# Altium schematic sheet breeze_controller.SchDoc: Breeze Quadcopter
size A4; Author: myyerrol; Organization: Team MicroDynamics; Address1: NWPU; Address2: Xi'an; Address3: Shannxi; Address4: China; Revision: V0.1; SheetNumber: 1; SheetTotal: 5
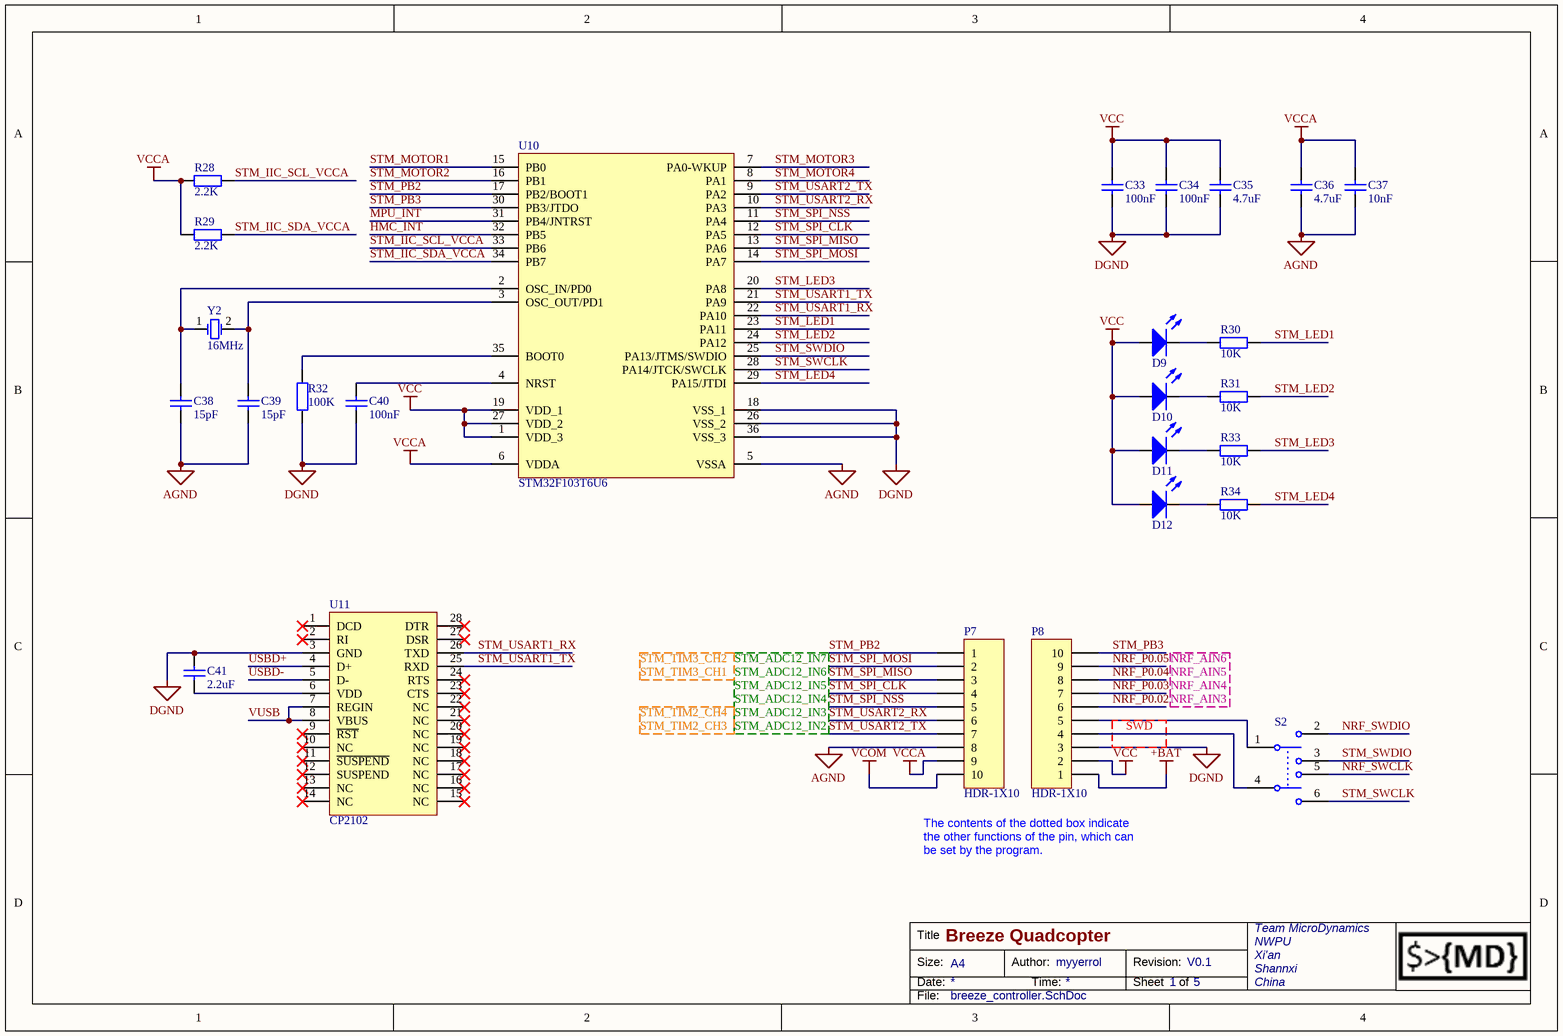
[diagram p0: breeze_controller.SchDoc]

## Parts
C33  value 100nF  [SMD-0603]  (hidden comment: CAP-0603)
C34  value 100nF  [SMD-0603]  (hidden comment: CAP-0603)
C35  value 4.7uF  [SMD-0603]  (hidden comment: CAP-0603)
C36  value 4.7uF  [SMD-0603]  (hidden comment: CAP-0603)
C37  value 10nF  [SMD-0603]  (hidden comment: CAP-0603)
C38  value 15pF  [SMD-0603]  (hidden comment: CAP-0603)
C39  value 15pF  [SMD-0603]  (hidden comment: CAP-0603)
C40  value 100nF  [SMD-0603]  (hidden comment: CAP-0603)
C41  value 2.2uF  [SMD-0603]  (hidden comment: CAP-0603)
D9  LED-0603  [SMD-0603]  (value not drawn)
D10  LED-0603  [SMD-0603]  (value not drawn)
D11  LED-0603  [SMD-0603]  (value not drawn)
D12  LED-0603  [SMD-0603]  (value not drawn)
P7  HDR-1X10  [HDR-1X10]
P8  HDR-1X10  [HDR-1X10]
R28  value 2.2K  [SMD-0603]  (hidden comment: RES-0603)
R29  value 2.2K  [SMD-0603]  (hidden comment: RES-0603)
R30  value 10K  [SMD-0603]  (hidden comment: RES-0603)
R31  value 10K  [SMD-0603]  (hidden comment: RES-0603)
R32  value 100K  [SMD-0603]  (hidden comment: RES-0603)
R33  value 10K  [SMD-0603]  (hidden comment: RES-0603)
R34  value 10K  [SMD-0603]  (hidden comment: RES-0603)
S2  MSS-22D18G2  [MSS-22D18G2]  (value not drawn)
U10  STM32F103T6U6  [VFQFPN-36]
U11  CP2102  [QFN-28]
Y2  value 16MHz  [SMD-5032]  (hidden comment: XTAL-5032)

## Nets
+BAT: P8.1
AGND: C36.2 C37.2 C38.2 C39.2 P7.8 U10.5(VSSA)
DGND: C33.2 C34.2 C35.2 C40.2 C41.2 P8.3 R32.2 U10.18(VSS_1) U10.26(VSS_2) U10.36(VSS_3) U11.3(GND)
VCC: C33.1 C34.1 C35.1 D9.1(A) D10.1(A) D11.1(A) D12.1(A) P8.2 U10.1(VDD_3) U10.19(VDD_1) U10.27(VDD_2)
VCCA: C36.1 C37.1 P7.9 R28.1 R29.1 U10.6(VDDA)
VCOM: P7.10
HMC_INT: U10.32(PB5)
MPU_INT: U10.31(PB4/JNTRST)
NRF_P0.02: P8.6
NRF_P0.03: P8.7
NRF_P0.04: P8.8
NRF_P0.05: P8.9
NRF_SWCLK: S2.5
NRF_SWDIO: S2.2
STM_IIC_SCL_VCCA: R28.2 U10.33(PB6)
STM_IIC_SDA_VCCA: R29.2 U10.34(PB7)
STM_LED1: R30.2 U10.23(PA11)
STM_LED2: R31.2 U10.24(PA12)
STM_LED3: R33.2 U10.20(PA8)
STM_LED4: R34.2 U10.29(PA15/JTDI)
STM_MOTOR1: U10.15(PB0)
STM_MOTOR2: U10.16(PB1)
STM_MOTOR3: U10.7(PA0-WKUP)
STM_MOTOR4: U10.8(PA1)
STM_PB2: P7.1 U10.17(PB2/BOOT1)
STM_PB3: P8.10 U10.30(PB3/JTDO)
STM_SPI_CLK: P7.4 U10.12(PA5)
STM_SPI_MISO: P7.3 U10.13(PA6)
STM_SPI_MOSI: P7.2 U10.14(PA7)
STM_SPI_NSS: P7.5 U10.11(PA4)
STM_SWCLK: S2.6 U10.28(PA14/JTCK/SWCLK)
STM_SWDIO: S2.3 U10.25(PA13/JTMS/SWDIO)
STM_USART1_RX: U10.22(PA10) U11.26(TXD)
STM_USART1_TX: U10.21(PA9) U11.25(RXD)
STM_USART2_RX: P7.6 U10.10(PA3)
STM_USART2_TX: P7.7 U10.9(PA2)
USBD+: U11.4(D+)
USBD-: U11.5(D-)
VUSB: U11.7(REGIN) U11.8(VBUS)
NetC38_1: C38.1 U10.2(OSC_IN/PD0) Y2.1(OSC1)
NetC39_1: C39.1 U10.3(OSC_OUT/PD1) Y2.2(OSC2)
NetC40_1: C40.1 U10.4(NRST)
NetC41_1: C41.1 U11.6(VDD)
NetD9_2: D9.2(K) R30.1
NetD10_2: D10.2(K) R31.1
NetD11_2: D11.2(K) R33.1
NetD12_2: D12.2(K) R34.1
NetP8_4: P8.4 S2.4
NetP8_5: P8.5 S2.1
NetR32_1: R32.1 U10.35(BOOT0)

Not connected (* = marked no-connect by the designer): U11 1(DCD)* 2(RI)* 9(~{RST})* 10(NC)* 11(~{SUSPEND})* 12(SUSPEND)* 13(NC)* 14(NC)* 15(NC)* 16(NC)* 17(NC)* 18(NC)* 19(NC)* 20(NC)* 21(NC)* 22(NC)* 23(CTS)* 24(RTS)* 27(DSR)* 28(DTR)*

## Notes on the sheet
- STM_TIM3_CH2
- STM_TIM3_CH1
- STM_TIM2_CH4
- STM_ADC12_IN6
- STM_ADC12_IN5
- STM_ADC12_IN4
- STM_ADC12_IN3
- STM_ADC12_IN7
- NRF_AIN6
- NRF_AIN5
- NRF_AIN4
- NRF_AIN3
- STM_TIM2_CH3
- STM_ADC12_IN2
- SWD
- The contents of the dotted box indicate the other functions of the pin, which can be set by the program.

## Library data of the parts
C33-C41 = CAP-0603: Capacitor
D9-D12 = LED-0603: LED
P7 P8 = HDR-1X10: Header 1X10
R28-R34 = RES-0603: Resistor
S2 = MSS-22D18G2: Double-Pole, Double-Throw Switch
U10 = STM32F103T6U6: ARM Cortex-M3 MCU
U11 = CP2102: Highly-integrated USB-to-UART Bridge Controller
Y2 = XTAL-5032: Passive Crystal Oscillator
